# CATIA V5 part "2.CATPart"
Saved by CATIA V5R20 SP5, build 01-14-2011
Part number: 2
Bounding box of the stored display mesh (mm): x -193 to 0, y -5 to 5, z -5 to 5
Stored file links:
  E:\IAO_2010\iao\IAO_MMS_Groupe2\IAO_MMS_Groupe2\melguidj\Catia\2.CATPart
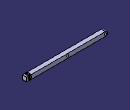
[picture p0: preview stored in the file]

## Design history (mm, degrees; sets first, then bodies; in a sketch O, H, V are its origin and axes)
Parameters
  AE2 = 180 mm
  AD2 = 90 mm
Body1 (main body)
  Sketch1 on zx-plane, origin (0, 0, 0), H (-1, 0, 0), V (0, 0, 1)
    point P1 (0, 5)
    line L1 (0, 5) -> (188, 5)
    line L2 (188, -5) -> (0, -5)
    line L3 (0, -5) -> (0, -4.5)
    point P4 (0, -5)
    circle A1 centre (98, 0) radius 2.5
    point P5 (98, 0)
    point P6 (100.5, 0)
    circle A2 centre (188, 0) radius 2.5
    point P7 (188, 0)
    point P8 (190.5, 0)
    arc A3 centre (188, 0) radius 5 from (188, 5) to (188, -5) cw
    point P9 (188, 0)
    point P10 (20, -4.5)
    point P11 (0, -4.5)
    point P12 (0, 4.5)
    line L4 (0, 4.5) -> (0, 5)
    line L5 (0, 4.5) -> (0, -4.5)
    axis line L6 (8, 19.3169) -> (8, -28.4964)
    distance H L1 = 5
    radius A1 = 2.5
    radius A2 = 2.5
    distance P4 P1 = 10
    distance P10 P11 = 20
    distance L6 L5 = 8
    distance L6 P5 = 90 {= AD2}
    distance P7 L6 = 180 {= AE2}
    horizontal: L1 H, L2 H
    vertical: L3 V, L4 V, L5 V, L6 V
    coincidence: L3 V, P5 H, A1 P6, P6 H, P7 H, A2 P8, P8 H, P9 P7, L3 P12, L3 L4
    tangency: A3 L2
  Pad1: profile Sketch1, direction (0, 1, 0), length 5, mirrored extent
  Sketch2 on face of Pad1 from Sketch1.L1, origin (0, 0, 5), H (1, 0, 0), V (0, 1, 0)
    circle A1 centre (-8, 0) radius 4
    point P1 (-8, 0)
    radius A1 = 4
    distance V P1 = 8
    coincidence: P1 H
  Pocket1: profile Sketch2, direction (0, 0, -1), through (limit type 3)
  Sketch3 on start face of Pad1, origin (0, -5, 0), H (1, 0, 0), V (0, 0, 1)
    circle A1 centre (-8, 0) radius 4
    point P1 (-8, 0)
    reference projected line E1 through (-8, 0) direction (0, 1) from axis of face of Pocket1 from Sketch2.A1
    radius A1 = 4
    coincidence: P1 H, P1 E1
  Pocket2: profile Sketch3, direction (0, 1, 0), through (limit type 3)
  Sketch4 on zx-plane, origin (0, 0, 0), H (-1, 0, 0), V (0, 0, 1)
    point P1 (8, 0)
    reference projected circle E1 centre (8, 0) radius 4 from edge [end face of Pad1 | face of Pocket2 from Sketch3.A1]
    concentricity: P1 E1
  DatumSurface1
